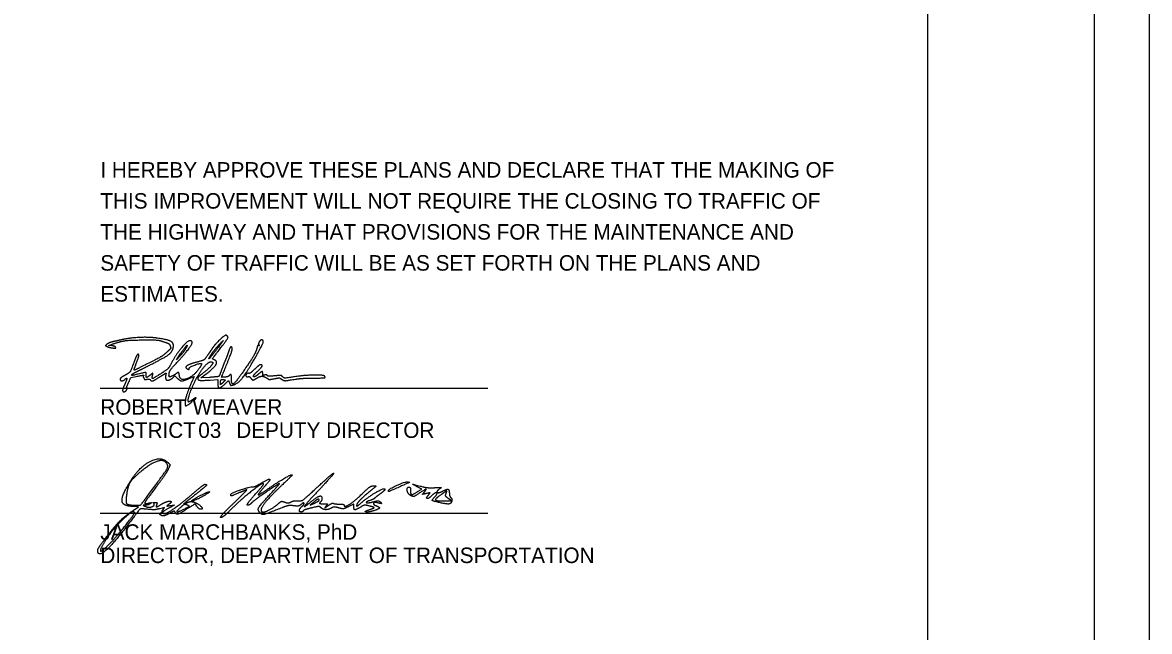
# Model space of a CAD drawing. Extents: x 0 to 34, y 0 to 22.
# Drawn here: x 23.83 to 34, y 5.5 to 11 of the extents above; entities that cross this region are included whole.
import ezdxf

# ---------------------------------------------------------------- set-up
doc = ezdxf.new("R2010")
doc.units = 0
for name, color, linetype in [('SH_Border', 7, 'Continuous'), ('SH_Cut_Line', 7, 'Continuous'), ('SH_Data', 7, 'Continuous'), ('SH_Text', 7, 'Continuous')]:
    doc.layers.add(name, color=color, linetype=linetype)

msp = doc.modelspace()

# ---------------------------------------------------------------- linework, layer by layer
at = {"layer": 'SH_Border'}
msp.add_line((32, 0.5), (32, 21.5), dxfattribs=at)
msp.add_lwpolyline([(1.5, 21.5), (33.5, 21.5), (33.5, 0.5), (1.5, 0.5)], close=True, dxfattribs=at)
at = {"layer": 'SH_Cut_Line'}
msp.add_lwpolyline([(0, 0), (34, 0), (34, 22), (0, 22)], close=True, dxfattribs=at)
at = {"layer": 'SH_Data'}
for p, q in [((24.528, 7.698), (28.028, 7.698)), ((24.528, 6.568), (28.028, 6.568))]:
    msp.add_line(p, q, dxfattribs=at)
at = {"layer": 'SH_Text'}
for p, q in [((24.99, 6.773), (24.99, 6.773)), ((27.129, 6.772), (27.129, 6.772)), ((25.311, 6.642), (25.311, 6.642)), ((25.356, 6.683), (25.356, 6.683)), ((25.727, 6.654), (25.727, 6.654)), ((26.504, 6.685), (26.504, 6.685)), ((27.582, 6.666), (27.582, 6.666))]:
    msp.add_line(p, q, dxfattribs=at)
for points in [[(24.633, 8.08), (24.603, 8.084), (24.63, 8.093)], [(25.249, 7.99), (25.216, 7.954), (25.256, 8.013)], [(24.782, 7.746), (24.803, 7.794), (24.852, 7.803)], [(25.182, 7.791), (25.202, 7.808), (25.223, 7.788)], [(25.331, 7.785), (25.374, 7.803), (25.349, 7.744)], [(25.514, 7.795), (25.435, 7.79), (25.484, 7.827)], [(25.521, 7.771), (25.59, 7.776), (25.59, 7.738)], [(25.636, 7.749), (25.613, 7.727), (25.613, 7.747)], [(25.662, 7.744), (25.684, 7.768), (25.694, 7.745)], [(27.393, 6.763), (27.43, 6.784), (27.389, 6.807)], [(24.843, 6.606), (24.873, 6.627), (24.835, 6.628)], [(25.085, 6.586), (25.107, 6.619), (25.065, 6.609)], [(26.453, 6.666), (26.423, 6.64), (26.464, 6.66)], [(27.642, 6.679), (27.698, 6.679), (27.669, 6.701)]]:
    msp.add_lwpolyline(points, dxfattribs=at)
for points in [[(25.045, 8.149), (24.973, 8.159), (24.809, 8.153), (24.736, 8.138)], [(25.183, 8.051), (25.197, 8.098), (25.145, 8.135), (25.045, 8.149)], [(25.665, 8.176), (25.656, 8.181), (25.569, 8.1), (25.541, 8.06)], [(25.591, 8.03), (25.672, 8.135), (25.686, 8.163), (25.665, 8.176)], [(24.59, 8.096), (24.574, 8.082), (24.574, 8.082), (24.588, 8.074)], [(24.588, 8.074), (24.596, 8.07), (24.618, 8.064), (24.636, 8.061)], [(24.647, 8.118), (24.625, 8.113), (24.6, 8.103), (24.59, 8.096)], [(24.63, 8.093), (24.708, 8.12), (24.802, 8.133), (24.927, 8.133)], [(24.666, 8.066), (24.664, 8.072), (24.649, 8.078), (24.633, 8.08)], [(24.636, 8.061), (24.663, 8.057), (24.669, 8.058), (24.666, 8.066)], [(24.736, 8.138), (24.709, 8.132), (24.669, 8.123), (24.647, 8.118)], [(24.927, 8.133), (25.036, 8.133), (25.059, 8.131), (25.102, 8.116)], [(24.965, 7.901), (25.097, 7.968), (25.173, 8.019), (25.183, 8.051)], [(25.102, 8.116), (25.142, 8.102), (25.153, 8.095), (25.159, 8.078)], [(25.159, 8.078), (25.165, 8.06), (25.163, 8.055), (25.143, 8.036)], [(25.336, 8.126), (25.312, 8.125), (25.202, 7.988), (25.161, 7.909)], [(25.228, 7.938), (25.322, 8.041), (25.371, 8.126), (25.336, 8.126)], [(25.295, 8.049), (25.287, 8.036), (25.267, 8.01), (25.249, 7.99)], [(25.256, 8.013), (25.295, 8.071), (25.322, 8.096), (25.295, 8.049)], [(25.541, 8.06), (25.532, 8.047), (25.512, 8.017), (25.495, 7.993)], [(25.572, 8.039), (25.526, 7.978), (25.499, 7.953), (25.526, 7.995)], [(25.526, 7.995), (25.544, 8.024), (25.584, 8.073), (25.615, 8.106)], [(25.615, 8.106), (25.644, 8.136), (25.628, 8.112), (25.572, 8.039)], [(25.675, 7.927), (25.712, 8.019), (25.723, 8.066), (25.708, 8.071)], [(25.708, 8.071), (25.704, 8.072), (25.694, 8.052), (25.685, 8.025)], [(25.944, 8.067), (25.936, 8.032), (25.895, 7.959), (25.836, 7.873)], [(25.928, 7.975), (25.988, 8.081), (26.006, 8.133), (25.983, 8.133)], [(25.957, 8.083), (25.952, 8.086), (25.946, 8.08), (25.944, 8.067)], [(25.983, 8.133), (25.971, 8.133), (25.953, 8.097), (25.96, 8.086)], [(25.96, 8.086), (25.963, 8.081), (25.962, 8.08), (25.957, 8.083)], [(24.836, 7.943), (24.803, 7.853), (24.793, 7.838), (24.748, 7.813)], [(24.866, 8.003), (24.861, 8.001), (24.847, 7.974), (24.836, 7.943)], [(24.849, 7.91), (24.873, 7.975), (24.879, 8.007), (24.866, 8.003)], [(25.143, 8.036), (25.105, 7.999), (25.056, 7.969), (24.944, 7.913)], [(25.148, 7.815), (25.148, 7.841), (25.169, 7.874), (25.228, 7.938)], [(25.434, 7.942), (25.371, 7.926), (25.306, 7.901), (25.302, 7.891)], [(25.495, 7.993), (25.471, 7.958), (25.46, 7.949), (25.434, 7.942)], [(25.484, 7.827), (25.559, 7.884), (25.589, 7.943), (25.552, 7.956)], [(25.552, 7.956), (25.539, 7.961), (25.543, 7.969), (25.591, 8.03)], [(25.655, 7.947), (25.648, 7.93), (25.633, 7.892), (25.623, 7.863)], [(25.685, 8.025), (25.676, 7.999), (25.662, 7.963), (25.655, 7.947)], [(25.725, 7.726), (25.768, 7.737), (25.848, 7.834), (25.928, 7.975)], [(24.813, 7.819), (24.813, 7.822), (24.827, 7.832), (24.845, 7.841)], [(24.833, 7.859), (24.831, 7.859), (24.838, 7.882), (24.849, 7.91)], [(24.944, 7.913), (24.885, 7.883), (24.835, 7.859), (24.833, 7.859)], [(24.845, 7.841), (24.863, 7.85), (24.917, 7.877), (24.965, 7.901)], [(24.942, 7.817), (24.942, 7.84), (24.935, 7.84), (24.87, 7.825)], [(25.161, 7.909), (25.147, 7.881), (25.123, 7.859), (25.062, 7.82)], [(25.241, 7.815), (25.238, 7.84), (25.231, 7.841), (25.203, 7.822)], [(25.424, 7.88), (25.371, 7.804), (25.247, 7.76), (25.241, 7.815)], [(25.302, 7.891), (25.3, 7.885), (25.303, 7.877), (25.309, 7.874)], [(25.309, 7.874), (25.324, 7.864), (25.331, 7.865), (25.331, 7.877)], [(25.331, 7.877), (25.331, 7.888), (25.433, 7.926), (25.442, 7.918)], [(25.413, 7.815), (25.446, 7.872), (25.506, 7.935), (25.526, 7.935)], [(25.442, 7.918), (25.444, 7.916), (25.436, 7.898), (25.424, 7.88)], [(25.544, 7.928), (25.544, 7.915), (25.494, 7.863), (25.449, 7.828)], [(25.526, 7.935), (25.536, 7.935), (25.544, 7.932), (25.544, 7.928)], [(25.623, 7.863), (25.612, 7.833), (25.601, 7.807), (25.598, 7.805)], [(25.653, 7.798), (25.622, 7.798), (25.621, 7.79), (25.675, 7.927)], [(25.836, 7.873), (25.754, 7.754), (25.712, 7.723), (25.712, 7.782)], [(25.921, 7.868), (25.895, 7.843), (25.874, 7.829), (25.868, 7.831)], [(25.91, 7.807), (25.91, 7.811), (25.927, 7.831), (25.949, 7.852)], [(25.972, 7.909), (25.967, 7.909), (25.944, 7.89), (25.921, 7.868)], [(25.949, 7.852), (25.984, 7.885), (25.994, 7.909), (25.972, 7.909)], [(25.994, 7.828), (25.994, 7.848), (25.983, 7.848), (25.959, 7.827)], [(24.748, 7.813), (24.725, 7.8), (24.706, 7.784), (24.706, 7.778)], [(24.706, 7.778), (24.706, 7.765), (24.737, 7.764), (24.75, 7.777)], [(24.749, 7.733), (24.738, 7.709), (24.729, 7.685), (24.729, 7.679)], [(24.75, 7.777), (24.768, 7.795), (24.768, 7.775), (24.749, 7.733)], [(24.768, 7.699), (24.764, 7.699), (24.77, 7.72), (24.782, 7.746)], [(24.87, 7.825), (24.817, 7.812), (24.813, 7.811), (24.813, 7.819)], [(24.852, 7.803), (24.908, 7.814), (24.924, 7.815), (24.917, 7.808)], [(24.917, 7.808), (24.914, 7.806), (24.916, 7.797), (24.92, 7.789)], [(24.92, 7.789), (24.926, 7.777), (24.933, 7.775), (24.95, 7.778)], [(24.975, 7.813), (24.949, 7.793), (24.942, 7.794), (24.942, 7.817)], [(24.95, 7.778), (24.962, 7.78), (24.974, 7.779), (24.977, 7.775)], [(24.999, 7.809), (25.004, 7.833), (25, 7.833), (24.975, 7.813)], [(24.977, 7.775), (24.986, 7.76), (25.017, 7.768), (25.061, 7.797)], [(25.062, 7.82), (25.007, 7.785), (24.992, 7.782), (24.999, 7.809)], [(25.061, 7.797), (25.086, 7.812), (25.11, 7.828), (25.114, 7.831)], [(25.114, 7.831), (25.12, 7.834), (25.122, 7.829), (25.119, 7.817)], [(25.119, 7.817), (25.112, 7.777), (25.146, 7.763), (25.182, 7.791)], [(25.165, 7.802), (25.151, 7.798), (25.148, 7.8), (25.148, 7.815)], [(25.203, 7.822), (25.191, 7.814), (25.174, 7.805), (25.165, 7.802)], [(25.223, 7.788), (25.249, 7.763), (25.275, 7.762), (25.331, 7.785)], [(25.349, 7.744), (25.317, 7.668), (25.293, 7.589), (25.293, 7.561)], [(25.325, 7.573), (25.313, 7.585), (25.371, 7.744), (25.413, 7.815)], [(25.449, 7.828), (25.426, 7.811), (25.407, 7.792), (25.407, 7.786)], [(25.407, 7.786), (25.407, 7.771), (25.447, 7.766), (25.521, 7.771)], [(25.598, 7.805), (25.596, 7.802), (25.558, 7.798), (25.514, 7.795)], [(25.59, 7.738), (25.59, 7.716), (25.592, 7.699), (25.594, 7.699)], [(25.594, 7.699), (25.605, 7.699), (25.642, 7.723), (25.662, 7.744)], [(25.613, 7.747), (25.613, 7.769), (25.625, 7.778), (25.647, 7.774)], [(25.647, 7.774), (25.657, 7.772), (25.655, 7.767), (25.636, 7.749)], [(25.689, 7.809), (25.684, 7.803), (25.667, 7.798), (25.653, 7.798)], [(25.712, 7.782), (25.712, 7.816), (25.703, 7.826), (25.689, 7.809)], [(25.694, 7.745), (25.702, 7.724), (25.706, 7.722), (25.725, 7.726)], [(25.868, 7.831), (25.854, 7.836), (25.837, 7.809), (25.849, 7.802)], [(25.849, 7.802), (25.853, 7.799), (25.86, 7.799), (25.865, 7.802)], [(25.865, 7.802), (25.869, 7.805), (25.878, 7.8), (25.884, 7.791)], [(25.884, 7.791), (25.898, 7.771), (25.915, 7.771), (25.943, 7.79)], [(25.959, 7.827), (25.935, 7.806), (25.91, 7.795), (25.91, 7.807)], [(25.943, 7.79), (25.968, 7.806), (26.008, 7.804), (26.037, 7.785)], [(26.012, 7.816), (25.997, 7.812), (25.994, 7.814), (25.994, 7.828)], [(26.036, 7.812), (26.033, 7.817), (26.023, 7.819), (26.012, 7.816)], [(26.102, 7.809), (26.06, 7.805), (26.04, 7.806), (26.036, 7.812)], [(26.037, 7.785), (26.05, 7.776), (26.061, 7.776), (26.099, 7.783)], [(26.099, 7.783), (26.138, 7.791), (26.147, 7.791), (26.162, 7.78)], [(26.174, 7.801), (26.164, 7.812), (26.152, 7.813), (26.102, 7.809)], [(26.162, 7.78), (26.184, 7.765), (26.207, 7.765), (26.291, 7.779)], [(26.317, 7.805), (26.195, 7.788), (26.188, 7.788), (26.174, 7.801)], [(26.291, 7.779), (26.326, 7.784), (26.397, 7.789), (26.448, 7.789)], [(26.553, 7.806), (26.547, 7.816), (26.386, 7.815), (26.317, 7.805)], [(26.448, 7.789), (26.54, 7.789), (26.562, 7.792), (26.553, 7.806)], [(24.729, 7.679), (24.729, 7.663), (24.758, 7.667), (24.767, 7.684)], [(24.767, 7.684), (24.772, 7.693), (24.772, 7.699), (24.768, 7.699)], [(25.293, 7.561), (25.293, 7.549), (25.295, 7.539), (25.298, 7.539)], [(25.298, 7.539), (25.308, 7.539), (25.354, 7.569), (25.354, 7.576)], [(25.36, 7.593), (25.342, 7.58), (25.326, 7.571), (25.325, 7.573)], [(25.354, 7.576), (25.354, 7.579), (25.362, 7.586), (25.373, 7.591)], [(25.392, 7.608), (25.392, 7.613), (25.377, 7.606), (25.36, 7.593)], [(25.373, 7.591), (25.383, 7.596), (25.392, 7.603), (25.392, 7.608)], [(24.779, 6.824), (24.865, 6.974), (25.073, 7.09), (25.139, 7.025)], [(25.13, 7.015), (25.104, 7.057), (24.978, 7.016), (24.883, 6.935)], [(25.139, 7.025), (25.158, 7.006), (25.158, 7.001), (25.139, 6.962)], [(24.883, 6.935), (24.816, 6.878), (24.777, 6.814), (24.766, 6.742)], [(24.99, 6.773), (25.112, 6.937), (25.144, 6.993), (25.13, 7.015)], [(25.139, 6.962), (25.128, 6.939), (25.077, 6.864), (25.024, 6.795)], [(26.487, 6.803), (26.562, 6.872), (26.628, 6.929), (26.634, 6.929)], [(26.634, 6.929), (26.639, 6.929), (26.587, 6.869), (26.518, 6.795)], [(24.835, 6.628), (24.737, 6.63), (24.714, 6.711), (24.779, 6.824)], [(25.369, 6.75), (25.419, 6.793), (25.465, 6.828), (25.47, 6.829)], [(25.47, 6.829), (25.495, 6.829), (25.472, 6.803), (25.386, 6.736)], [(26.002, 6.836), (25.992, 6.845), (25.782, 6.678), (25.704, 6.599)], [(26.142, 6.835), (26.093, 6.807), (25.905, 6.675), (25.891, 6.659)], [(25.908, 6.807), (25.914, 6.805), (25.943, 6.818), (25.974, 6.836)], [(25.924, 6.735), (25.97, 6.787), (26.005, 6.832), (26.002, 6.836)], [(25.974, 6.836), (26.052, 6.882), (26.065, 6.869), (26.005, 6.802)], [(26.168, 6.822), (26.069, 6.728), (25.979, 6.62), (25.979, 6.593)], [(26.033, 6.782), (26.113, 6.839), (26.244, 6.916), (26.26, 6.916)], [(26.077, 6.756), (26.123, 6.806), (26.152, 6.841), (26.142, 6.835)], [(26.26, 6.916), (26.265, 6.916), (26.224, 6.874), (26.168, 6.822)], [(27.129, 6.772), (27.129, 6.785), (27.282, 6.855), (27.301, 6.851)], [(27.301, 6.851), (27.322, 6.847), (27.323, 6.848), (27.201, 6.793)], [(27.389, 6.807), (27.346, 6.831), (27.345, 6.831), (27.448, 6.805)], [(24.766, 6.742), (24.755, 6.669), (24.776, 6.641), (24.844, 6.641)], [(24.844, 6.641), (24.891, 6.641), (24.895, 6.645), (24.99, 6.773)], [(25.024, 6.795), (24.972, 6.725), (24.929, 6.664), (24.929, 6.66)], [(25.108, 6.566), (25.131, 6.566), (25.257, 6.655), (25.369, 6.75)], [(25.386, 6.736), (25.293, 6.663), (25.271, 6.642), (25.315, 6.665)], [(25.356, 6.683), (25.376, 6.701), (25.508, 6.767), (25.513, 6.762)], [(25.513, 6.762), (25.519, 6.756), (25.377, 6.679), (25.359, 6.679)], [(25.705, 6.738), (25.705, 6.749), (25.892, 6.812), (25.908, 6.807)], [(25.786, 6.754), (25.723, 6.727), (25.704, 6.723), (25.705, 6.738)], [(25.727, 6.654), (25.798, 6.723), (25.854, 6.779), (25.85, 6.779)], [(25.85, 6.779), (25.847, 6.779), (25.818, 6.767), (25.786, 6.754)], [(25.858, 6.641), (25.848, 6.641), (25.877, 6.683), (25.924, 6.735)], [(26.005, 6.802), (25.977, 6.77), (25.954, 6.74), (25.954, 6.736)], [(25.954, 6.736), (25.954, 6.731), (25.99, 6.752), (26.033, 6.782)], [(25.97, 6.571), (25.945, 6.596), (25.973, 6.646), (26.077, 6.756)], [(26.312, 6.68), (26.345, 6.678), (26.369, 6.694), (26.487, 6.803)], [(26.518, 6.795), (26.388, 6.657), (26.356, 6.61), (26.439, 6.678)], [(26.439, 6.678), (26.487, 6.718), (26.529, 6.728), (26.529, 6.7)], [(26.729, 6.64), (26.729, 6.617), (26.825, 6.678), (26.895, 6.747)], [(26.967, 6.769), (26.893, 6.708), (26.842, 6.654), (26.842, 6.638)], [(26.876, 6.655), (26.93, 6.704), (27.077, 6.794), (27.094, 6.789)], [(26.895, 6.747), (26.94, 6.79), (26.977, 6.816), (26.995, 6.816)], [(26.995, 6.816), (27.019, 6.815), (27.016, 6.809), (26.967, 6.769)], [(27.06, 6.747), (27.033, 6.727), (27.008, 6.707), (27.004, 6.702)], [(27.094, 6.789), (27.102, 6.786), (27.087, 6.767), (27.06, 6.747)], [(27.201, 6.793), (27.138, 6.765), (27.129, 6.762), (27.129, 6.772)], [(27.33, 6.728), (27.304, 6.742), (27.293, 6.804), (27.317, 6.804)], [(27.317, 6.804), (27.324, 6.804), (27.329, 6.79), (27.329, 6.772)], [(27.329, 6.772), (27.329, 6.736), (27.344, 6.733), (27.393, 6.763)], [(27.405, 6.747), (27.365, 6.72), (27.352, 6.717), (27.33, 6.728)], [(27.453, 6.758), (27.477, 6.788), (27.461, 6.784), (27.405, 6.747)], [(27.472, 6.746), (27.439, 6.738), (27.437, 6.739), (27.453, 6.758)], [(27.448, 6.805), (27.469, 6.8), (27.514, 6.797), (27.548, 6.799)], [(27.492, 6.735), (27.507, 6.753), (27.505, 6.754), (27.472, 6.746)], [(27.521, 6.727), (27.489, 6.697), (27.466, 6.704), (27.492, 6.735)], [(27.546, 6.714), (27.577, 6.748), (27.555, 6.759), (27.521, 6.727)], [(27.548, 6.799), (27.603, 6.802), (27.608, 6.8), (27.588, 6.785)], [(27.589, 6.724), (27.546, 6.693), (27.563, 6.679), (27.642, 6.679)], [(27.588, 6.785), (27.559, 6.764), (27.582, 6.748), (27.616, 6.766)], [(27.65, 6.747), (27.66, 6.773), (27.651, 6.77), (27.589, 6.724)], [(27.616, 6.766), (27.656, 6.787), (27.679, 6.781), (27.679, 6.75)], [(27.669, 6.701), (27.649, 6.717), (27.643, 6.73), (27.65, 6.747)], [(27.679, 6.75), (27.679, 6.734), (27.686, 6.715), (27.694, 6.707)], [(24.936, 6.641), (24.913, 6.64), (24.914, 6.638), (24.94, 6.628)], [(24.929, 6.66), (24.929, 6.655), (24.945, 6.655), (24.964, 6.659)], [(24.979, 6.654), (24.969, 6.647), (24.949, 6.641), (24.936, 6.641)], [(24.94, 6.628), (24.97, 6.616), (25.026, 6.641), (25.009, 6.658)], [(24.964, 6.659), (24.989, 6.665), (24.993, 6.664), (24.979, 6.654)], [(25.009, 6.658), (25.004, 6.663), (25.01, 6.666), (25.022, 6.666)], [(25.022, 6.666), (25.037, 6.666), (25.042, 6.66), (25.037, 6.647)], [(25.037, 6.647), (25.029, 6.624), (25.041, 6.624), (25.074, 6.646)], [(25.074, 6.646), (25.102, 6.665), (25.167, 6.683), (25.167, 6.671)], [(25.152, 6.617), (25.101, 6.589), (25.081, 6.566), (25.108, 6.566)], [(25.145, 6.647), (25.126, 6.633), (25.128, 6.632), (25.161, 6.637)], [(25.167, 6.671), (25.167, 6.666), (25.157, 6.656), (25.145, 6.647)], [(25.161, 6.637), (25.198, 6.642), (25.198, 6.642), (25.152, 6.617)], [(25.258, 6.625), (25.213, 6.585), (25.225, 6.576), (25.283, 6.605)], [(25.311, 6.642), (25.293, 6.648), (25.277, 6.643), (25.258, 6.625)], [(25.283, 6.605), (25.329, 6.629), (25.333, 6.634), (25.311, 6.642)], [(25.315, 6.665), (25.328, 6.672), (25.351, 6.674), (25.368, 6.67)], [(25.401, 6.628), (25.384, 6.652), (25.382, 6.652), (25.316, 6.61)], [(25.359, 6.679), (25.354, 6.679), (25.353, 6.681), (25.356, 6.683)], [(25.368, 6.67), (25.404, 6.661), (25.463, 6.604), (25.436, 6.604)], [(25.436, 6.604), (25.426, 6.604), (25.411, 6.615), (25.401, 6.628)], [(25.617, 6.529), (25.607, 6.53), (25.656, 6.586), (25.727, 6.654)], [(25.891, 6.659), (25.883, 6.649), (25.868, 6.641), (25.858, 6.641)], [(26.169, 6.618), (26.023, 6.56), (25.988, 6.552), (25.97, 6.571)], [(25.998, 6.579), (26.019, 6.579), (26.101, 6.624), (26.137, 6.656)], [(26.137, 6.656), (26.157, 6.674), (26.17, 6.677), (26.194, 6.668)], [(26.275, 6.635), (26.246, 6.639), (26.206, 6.633), (26.169, 6.618)], [(26.194, 6.668), (26.214, 6.66), (26.233, 6.661), (26.249, 6.67)], [(26.249, 6.67), (26.262, 6.677), (26.291, 6.682), (26.312, 6.68)], [(26.344, 6.65), (26.329, 6.636), (26.307, 6.631), (26.275, 6.635)], [(26.341, 6.579), (26.323, 6.579), (26.327, 6.611), (26.348, 6.629)], [(26.367, 6.657), (26.367, 6.664), (26.357, 6.661), (26.344, 6.65)], [(26.348, 6.629), (26.359, 6.637), (26.367, 6.65), (26.367, 6.657)], [(26.436, 6.616), (26.397, 6.607), (26.363, 6.595), (26.359, 6.589)], [(26.52, 6.618), (26.509, 6.629), (26.489, 6.629), (26.436, 6.616)], [(26.504, 6.685), (26.504, 6.699), (26.48, 6.69), (26.453, 6.666)], [(26.464, 6.66), (26.486, 6.671), (26.504, 6.682), (26.504, 6.685)], [(26.514, 6.669), (26.503, 6.657), (26.509, 6.654), (26.541, 6.654)], [(26.529, 6.7), (26.529, 6.691), (26.523, 6.677), (26.514, 6.669)], [(26.616, 6.616), (26.585, 6.599), (26.538, 6.601), (26.52, 6.618)], [(26.541, 6.654), (26.579, 6.654), (26.581, 6.652), (26.565, 6.632)], [(26.565, 6.632), (26.553, 6.617), (26.56, 6.619), (26.587, 6.638)], [(26.587, 6.638), (26.609, 6.653), (26.629, 6.662), (26.633, 6.658)], [(26.681, 6.616), (26.654, 6.624), (26.631, 6.624), (26.616, 6.616)], [(26.633, 6.658), (26.637, 6.654), (26.66, 6.651), (26.685, 6.651)], [(26.77, 6.627), (26.732, 6.609), (26.714, 6.606), (26.681, 6.616)], [(26.685, 6.651), (26.709, 6.651), (26.729, 6.646), (26.729, 6.64)], [(26.817, 6.627), (26.817, 6.65), (26.816, 6.65), (26.77, 6.627)], [(26.879, 6.624), (26.834, 6.598), (26.817, 6.598), (26.817, 6.627)], [(26.842, 6.638), (26.842, 6.63), (26.857, 6.638), (26.876, 6.655)], [(26.962, 6.632), (26.923, 6.642), (26.906, 6.64), (26.879, 6.624)], [(26.97, 6.686), (26.921, 6.67), (26.94, 6.657), (26.992, 6.671)], [(26.992, 6.613), (27.003, 6.617), (26.992, 6.625), (26.962, 6.632)], [(27.004, 6.702), (27.001, 6.698), (26.986, 6.691), (26.97, 6.686)], [(26.992, 6.671), (27.03, 6.681), (27.045, 6.68), (27.058, 6.668)], [(27.039, 6.66), (27.002, 6.67), (26.989, 6.646), (27.023, 6.633)], [(27.023, 6.633), (27.054, 6.622), (27.045, 6.607), (26.998, 6.591)], [(27.058, 6.668), (27.07, 6.655), (27.067, 6.654), (27.039, 6.66)], [(27.582, 6.666), (27.527, 6.679), (27.522, 6.687), (27.546, 6.714)], [(27.7, 6.673), (27.692, 6.652), (27.651, 6.65), (27.582, 6.666)], [(27.694, 6.707), (27.701, 6.699), (27.704, 6.684), (27.7, 6.673)], [(24.835, 6.577), (24.814, 6.598), (24.596, 6.372), (24.55, 6.282)], [(24.592, 6.364), (24.669, 6.464), (24.749, 6.542), (24.843, 6.606)], [(24.62, 6.301), (24.687, 6.37), (24.843, 6.569), (24.835, 6.577)], [(24.924, 6.606), (24.89, 6.61), (24.879, 6.599), (24.802, 6.497)], [(25.065, 6.609), (25.025, 6.599), (25.002, 6.599), (24.924, 6.606)], [(25.084, 6.546), (25.066, 6.553), (25.066, 6.557), (25.085, 6.586)], [(25.151, 6.566), (25.125, 6.551), (25.095, 6.542), (25.084, 6.546)], [(25.202, 6.58), (25.199, 6.588), (25.18, 6.583), (25.151, 6.566)], [(25.316, 6.61), (25.248, 6.565), (25.21, 6.556), (25.202, 6.58)], [(25.704, 6.599), (25.667, 6.561), (25.627, 6.529), (25.617, 6.529)], [(25.979, 6.593), (25.979, 6.585), (25.988, 6.579), (25.998, 6.579)], [(26.359, 6.589), (26.356, 6.583), (26.348, 6.579), (26.341, 6.579)], [(26.998, 6.591), (26.952, 6.576), (26.904, 6.582), (26.948, 6.597)], [(26.948, 6.597), (26.962, 6.602), (26.982, 6.609), (26.992, 6.613)], [(24.802, 6.497), (24.65, 6.295), (24.504, 6.167), (24.504, 6.234)], [(24.504, 6.234), (24.504, 6.243), (24.544, 6.302), (24.592, 6.364)], [(24.55, 6.282), (24.518, 6.221), (24.55, 6.229), (24.62, 6.301)]]:
    msp.add_open_spline(points, degree=2, dxfattribs=at)

# ---------------------------------------------------------------- texts
for s, p in [('I HEREBY APPROVE THESE PLANS AND DECLARE THAT THE MAKING OF', (24.528, 9.599)), ('THIS IMPROVEMENT WILL NOT REQUIRE THE CLOSING TO TRAFFIC OF', (24.528, 9.319)), ('THE HIGHWAY AND THAT PROVISIONS FOR THE MAINTENANCE AND', (24.528, 9.039)), ('SAFETY OF TRAFFIC WILL BE AS SET FORTH ON THE PLANS AND', (24.528, 8.759)), ('ESTIMATES.', (24.528, 8.479)), ('ROBERT WEAVER', (24.528, 7.458)), ('DISTRICT       DEPUTY DIRECTOR', (24.528, 7.248)), ('                 03', (24.528, 7.248)), ('JACK MARCHBANKS, PhD', (24.528, 6.328)), ('DIRECTOR, DEPARTMENT OF TRANSPORTATION', (24.528, 6.118))]:
    msp.add_text(s, height=0.14, dxfattribs=at).set_placement(p)

doc.saveas('drawing.dxf')
